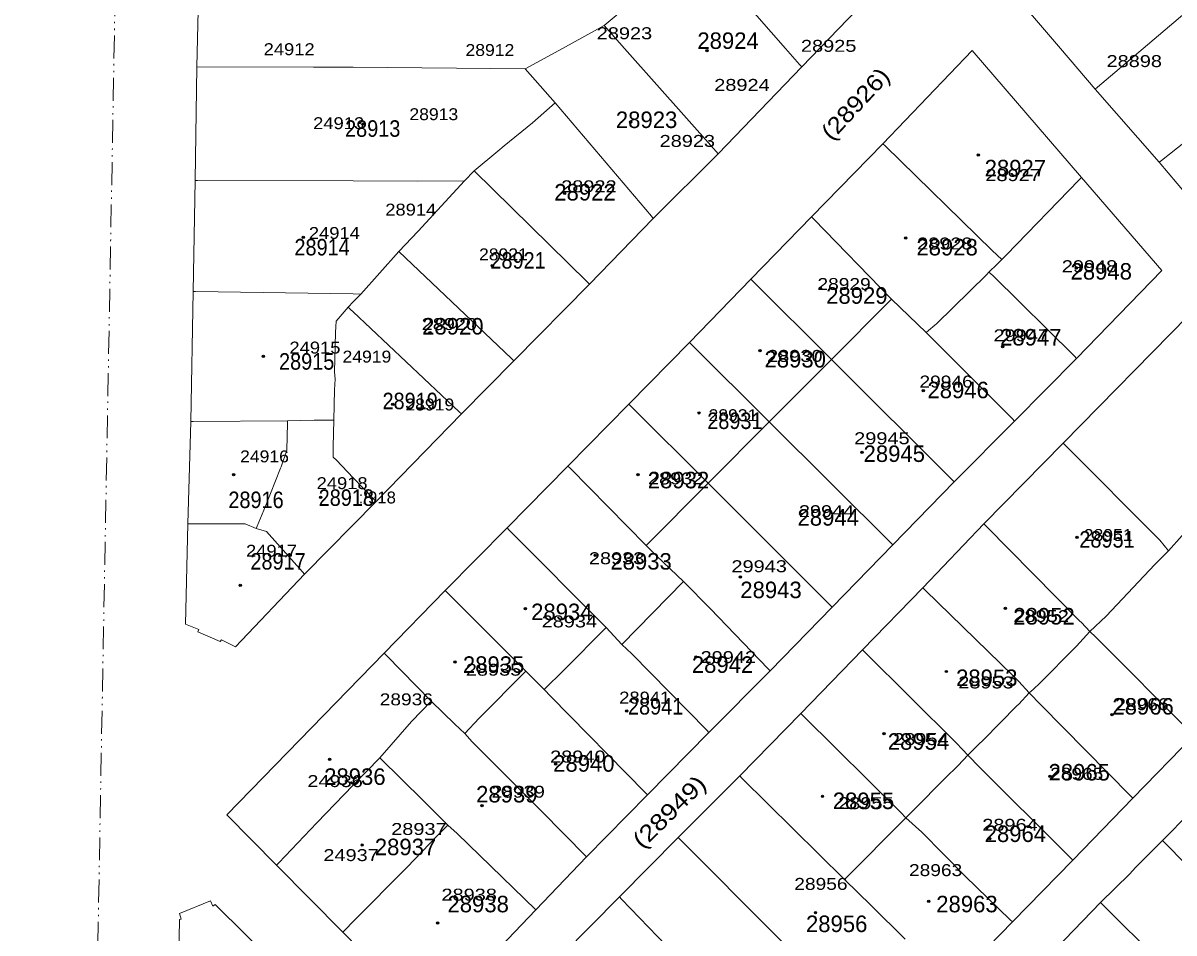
# Model space of a CAD drawing. Extents: x 650553 to 652508, y 239277 to 241647.
# Drawn here: x 650553 to 650803.9, y 240307.2 to 240505.5 of the extents above; entities that cross this region are included whole.
import ezdxf

# ---------------------------------------------------------------- set-up
doc = ezdxf.new("R2010")
doc.units = 0
doc.header["$PDMODE"] = 32
doc.header["$PDSIZE"] = 0.5
doc.linetypes.add('DASH_DOUBLE_DOT', pattern=[9.2, 5, -1.2, 0.3, -1.2, 0.3, -1.2])
for name, color, linetype in [('19', 7, 'Continuous'), ('20', 7, 'Continuous'), ('6', 7, 'Continuous')]:
    doc.layers.add(name, color=color, linetype=linetype)
for name, color, linetype, lineweight in [('3', 7, 'Continuous', 13), ('5', 7, 'Continuous', 13), ('52', 7, 'DASH_DOUBLE_DOT', 13)]:
    doc.layers.add(name, color=color, linetype=linetype, lineweight=lineweight)

msp = doc.modelspace()

# ---------------------------------------------------------------- linework, layer by layer
at = {"layer": '3'}
for p, q in [((650759.9, 240499.51), (650783.69, 240471.83)), ((650761.43, 240286.46), (650787.85, 240313.79))]:
    msp.add_line(p, q, dxfattribs=at)
for points in [[(650641.253, 240637.783), (650611.303, 240672.672), (650607.004, 240673.162), (650594.146, 240646.254), (650593.75, 240621.72), (650592.8, 240596.31), (650592.32, 240570.89), (650591.99, 240545.96), (650591.4, 240517.48), (650590.91, 240496.01)], [(650722.72, 240495.97), (650742.7, 240516.78), (650742.7, 240519.73), (650723.62, 240541.87), (650704.48, 240564.63), (650689.1, 240582.35), (650673.18, 240600.74), (650657.314, 240619.179), (650641.253, 240637.783)], [(650779.1, 240500), (650770.45, 240510.11), (650796.97, 240533.86), (650812.73, 240517.56)], [(650608.29, 240321.94), (650597.42, 240332.94), (650631.74, 240368.15), (650645.05, 240381.8), (650658.5, 240395.47), (650671.76, 240408.96), (650685.08, 240422.45), (650698.26, 240435.88), (650711.63, 240449.67), (650724.89, 240463.26), (650740.42, 240479.21), (650759.9, 240499.51)], [(650779.1, 240500), (650786.71, 240491.11), (650800.67, 240475.19), (650814.34, 240458.95), (650832.82, 240437.45)], [(650588.95, 240396.36), (650588.42, 240374.5), (650591.31, 240373.31), (650591.12, 240372.8), (650595.95, 240370.69), (650596.27, 240371.09), (650599.3, 240369.58), (650614.36, 240385.37), (650629.97, 240401.25), (650648.54, 240420.31), (650659.99, 240431.91), (650676.48, 240448.61), (650690.38, 240462.94), (650704.5, 240476.99), (650722.72, 240495.97)], [(650590.91, 240496.01), (650590.56, 240471.18), (650590.07, 240446.99), (650589.57, 240418.69), (650588.95, 240396.36)], [(650783.69, 240471.83), (650801.22, 240451.56), (650782.65, 240432.42), (650769.138, 240418.737), (650755.97, 240405.5), (650742.6, 240391.77), (650729.33, 240378.23), (650715.86, 240364.33), (650702.52, 240350.9), (650689.09, 240337.28), (650675.83, 240323.79), (650664.78, 240312.19), (650641.7, 240288.01), (650622.73, 240307.37), (650608.29, 240321.94)], [(650779.71, 240413.95), (650806.93, 240441.68), (650809.94, 240441.52), (650829.64, 240418.33), (650839.71, 240406.79), (650850.75, 240393.72), (650839.03, 240381.99), (650828.2, 240370.72), (650808.21, 240350.23), (650794.9, 240336.56), (650781.8, 240323.07), (650768.64, 240309.58), (650755.41, 240295.93), (650741.91, 240281.85), (650728.35, 240268.09)], [(650648.95, 240280.64), (650664.24, 240296.1), (650682.98, 240315.02), (650695.81, 240328), (650709.21, 240341.41), (650722.53, 240355.03), (650735.95, 240368.92), (650749.1, 240382.41), (650762.42, 240396.35), (650779.71, 240413.95)], [(650787.85, 240313.79), (650794.22, 240320.09), (650795.45, 240321.44), (650801.38, 240327.33), (650807.43, 240333.47), (650808.64, 240334.74), (650814.48, 240340.93), (650825.07, 240351.63), (650835.69, 240362.55), (650856.48, 240383.5), (650859.73, 240383.17), (650866.12, 240376.02), (650867.47, 240374.36), (650873.78, 240367.01), (650886.12, 240352.53), (650899.62, 240336.77), (650899.4, 240333.52)], [(650586.52, 240278.39), (650587.14, 240310.13), (650587.44, 240310.18), (650587.09, 240311.44), (650593.87, 240314.16), (650594.4, 240313.05), (650594.86, 240313.35), (650621.45, 240287.07), (650639.57, 240269.49), (650652.76, 240256.68), (650664.23, 240244.84), (650669.94, 240239.41), (650675.92, 240234.11), (650687.16, 240222.82), (650709.87, 240200.29), (650724.82, 240185.65), (650738.96, 240172.09)]]:
    msp.add_lwpolyline(points, dxfattribs=at)
at = {"layer": '5'}
for p, q in [((650670.56, 240500), (650662.43, 240495.54)), ((650763.49, 240451.21), (650764.41, 240450.46)), ((650626.62, 240446.45), (650625, 240446.47)), ((650625, 240444.73), (650623.91, 240443.57)), ((650683.55, 240370.08), (650696.94, 240383.82))]:
    msp.add_line(p, q, dxfattribs=at)
for points in [[(650679.64, 240504.99), (650699.96, 240521.98), (650719.19, 240500)], [(650797.15, 240500), (650814.38, 240514.674), (650814.88, 240515.1)], [(650670.56, 240500), (650679.64, 240504.99), (650684.07, 240500)], [(650684.07, 240500), (650704.056, 240477.49), (650704.5, 240476.99)], [(650719.19, 240500), (650722.282, 240496.47), (650722.72, 240495.97)], [(650786.71, 240491.11), (650787.21, 240491.536), (650797.15, 240500)], [(650830.23, 240498.54), (650829.73, 240498.145), (650801.17, 240475.585), (650800.67, 240475.19)], [(650590.91, 240496.01), (650616.34, 240495.92), (650625, 240495.87)], [(650625, 240495.87), (650662.43, 240495.54), (650669.01, 240488.12)], [(650625, 240444.73), (650626.62, 240446.45), (650634.91, 240455.7), (650639.15, 240460.13), (650649.22, 240471.15), (650651.36, 240473.31), (650656.46, 240477.59), (650657.9, 240478.76), (650664.02, 240483.74), (650669.01, 240488.12)], [(650669.01, 240488.12), (650689.956, 240463.44), (650690.38, 240462.94)], [(650740.42, 240479.21), (650740.92, 240478.72), (650764.21, 240455.91), (650766.32, 240453.97)], [(650651.36, 240473.31), (650675.98, 240449.102), (650676.48, 240448.61)], [(650590.56, 240471.18), (650591.06, 240471.179), (650625, 240471.11)], [(650625, 240471.11), (650638.91, 240471.08), (650649.22, 240471.15)], [(650783.69, 240471.83), (650783.205, 240471.33), (650767.31, 240454.94), (650766.32, 240453.97), (650765.33, 240452.97), (650763.49, 240451.21), (650763.04, 240450.64), (650752.07, 240439.93), (650751.72, 240439.69)], [(650724.89, 240463.26), (650725.375, 240462.76), (650742.29, 240445.32), (650749.83, 240438.07)], [(650634.91, 240455.7), (650659.49, 240432.384), (650659.99, 240431.91)], [(650764.41, 240450.46), (650782.15, 240432.915), (650782.65, 240432.42)], [(650711.63, 240449.67), (650712.13, 240449.172), (650729.19, 240432.178), (650755.97, 240405.5)], [(650590.07, 240446.99), (650590.57, 240446.983), (650625, 240446.47)], [(650729.19, 240432.178), (650741.792, 240444.82), (650742.29, 240445.32)], [(650623.91, 240443.57), (650621.24, 240440.54), (650621.1, 240438.07), (650620.91, 240429.48), (650621.01, 240427.92), (650620.9, 240425.54), (650620.77, 240418.93)], [(650623.91, 240443.57), (650624.41, 240443.098), (650625, 240442.54)], [(650625, 240442.54), (650648.04, 240420.782), (650648.54, 240420.31)], [(650751.72, 240439.69), (650750.33, 240438.499), (650749.83, 240438.07)], [(650749.83, 240438.07), (650768.639, 240419.237), (650769.138, 240418.737)], [(650698.26, 240435.88), (650698.76, 240435.383), (650715.643, 240418.588), (650742.6, 240391.77)], [(650688.8, 240391.66), (650702.319, 240405.222), (650715.643, 240418.588), (650729.19, 240432.178)], [(650685.08, 240422.45), (650685.58, 240421.95), (650702.319, 240405.222)], [(650589.57, 240418.69), (650590.07, 240418.692), (650610.67, 240418.78)], [(650610.67, 240418.78), (650610.66, 240418.28), (650610.54, 240412.42), (650609.24, 240408.77), (650609.13, 240408.53), (650605.85, 240400.24), (650604.055, 240395.86), (650603.85, 240395.36)], [(650610.67, 240418.78), (650616.47, 240418.95), (650620.27, 240418.932), (650620.77, 240418.93)], [(650620.77, 240418.93), (650620.61, 240413.24), (650620.6, 240410.88), (650621.3, 240410.23), (650625, 240406.4)], [(650779.71, 240413.95), (650780.208, 240413.45), (650800.78, 240392.81), (650802.7, 240390.51)], [(650671.76, 240408.96), (650672.252, 240408.46), (650688.8, 240391.66), (650691.1, 240389.42), (650696.94, 240383.82), (650702.83, 240377.81)], [(650625, 240406.4), (650629.487, 240401.75), (650629.97, 240401.25)], [(650702.319, 240405.222), (650728.83, 240378.73), (650729.33, 240378.23)], [(650785.52, 240372.91), (650789.1, 240376.24), (650799.71, 240387.51), (650802.7, 240390.51), (650805.63, 240393.83), (650816.46, 240404.86)], [(650588.95, 240396.36), (650589.45, 240396.36), (650601.41, 240396.37), (650603.85, 240395.36)], [(650603.85, 240395.36), (650606.1, 240394.66), (650613.915, 240385.87), (650614.36, 240385.37)], [(650658.5, 240395.47), (650658.998, 240394.97), (650680.11, 240373.79), (650683.55, 240370.08), (650685.71, 240368.03)], [(650762.42, 240396.35), (650762.913, 240395.85), (650783.25, 240375.23), (650783.74, 240374.83), (650785.52, 240372.91), (650786.82, 240371.66)], [(650749.1, 240382.41), (650749.6, 240381.923), (650768.78, 240363.24), (650770.08, 240361.96), (650772.29, 240359.53), (650774.86, 240356.94)], [(650645.05, 240381.8), (650645.55, 240381.301), (650662.61, 240364.28), (650666.61, 240360.28), (650668.07, 240358.73)], [(650702.83, 240377.81), (650715.377, 240364.83), (650715.86, 240364.33)], [(650666.61, 240360.28), (650670.88, 240364.49), (650680.11, 240373.79)], [(650732.07, 240318.85), (650745.43, 240332.28), (650747.17, 240334.04), (650754.02, 240340.91), (650756.82, 240343.66), (650758.96, 240345.93), (650761.22, 240348.21), (650762.32, 240349.26), (650769.63, 240356.69), (650770.08, 240357.05), (650772.29, 240359.53), (650773.2, 240360.26), (650774.7, 240361.72), (650782.3, 240369.37), (650782.59, 240369.7), (650785.52, 240372.91)], [(650786.82, 240371.66), (650807.711, 240350.73), (650808.21, 240350.23)], [(650631.74, 240368.15), (650632.229, 240367.65), (650641.98, 240357.69), (650647.14, 240352.68), (650649.28, 240350.65), (650650.87, 240348.81), (650665.93, 240333.82), (650675.83, 240323.79)], [(650685.71, 240368.03), (650702.029, 240351.4), (650702.52, 240350.9)], [(650735.95, 240368.92), (650736.45, 240368.423), (650756.39, 240348.6), (650757.79, 240347.14), (650758.96, 240345.93), (650760.09, 240344.79), (650760.36, 240344.44)], [(650649.28, 240350.65), (650652.4, 240354.03), (650662.61, 240364.28)], [(650625, 240339.4), (650630.75, 240345.37), (650637.71, 240353.26), (650641.98, 240357.69)], [(650668.07, 240358.73), (650688.6, 240337.78), (650689.09, 240337.28)], [(650722.53, 240355.03), (650723.03, 240354.534), (650744.32, 240333.43), (650745.43, 240332.28), (650748.94, 240329.16), (650758.33, 240319.53)], [(650774.86, 240356.94), (650794.408, 240337.06), (650794.9, 240336.56)], [(650630.75, 240345.37), (650640.27, 240335.98), (650645.6, 240330.68), (650647.65, 240328.89), (650664.78, 240312.19)], [(650760.36, 240344.44), (650781.3, 240323.568), (650781.8, 240323.07)], [(650709.21, 240341.41), (650709.71, 240340.917), (650732.07, 240318.85), (650737.83, 240313.19), (650745.26, 240305.8)], [(650608.29, 240321.94), (650608.765, 240322.44), (650617.07, 240331.18), (650625, 240339.4)], [(650625, 240309.66), (650636.71, 240321.51), (650643.17, 240328.27), (650645.6, 240330.68)], [(650695.81, 240328), (650696.307, 240327.5), (650717.06, 240306.61), (650721.14, 240302.53), (650725.63, 240298.21), (650726.33, 240297.51)], [(650801.38, 240327.33), (650823.52, 240304.87), (650847.74, 240281.16)], [(650758.33, 240319.53), (650768.14, 240310.063), (650768.64, 240309.58)], [(650682.98, 240315.02), (650683.461, 240314.52), (650699.12, 240298.24), (650707.18, 240290.13), (650712.21, 240284.96)], [(650787.85, 240313.79), (650801.15, 240300.62), (650809.97, 240291.87), (650834.26, 240267.54)], [(650622.73, 240307.37), (650623.226, 240307.87), (650625, 240309.66)]]:
    msp.add_lwpolyline(points, dxfattribs=at)
at = {"layer": '52'}
msp.add_lwpolyline([(650605.404, 240765.589), (650575.102, 240622.376), (650564.111, 240019.547), (650563.292, 239912.239), (650561.967, 239831.306), (650558.948, 239635.138), (650557.76, 239590.469), (650555.824, 239499.761), (650555.114, 239481.758), (650553.994, 239393.396), (650554.019, 239393.395), (650553.222, 239318.763), (650553.006, 239301.006), (650586.911, 239277.281)], dxfattribs=at)
at = {"layer": '6'}
for p in [(650702.084, 240499.485), (650627.257, 240483.545), (650685.422, 240483.965), (650761.206, 240476.74), (650671.083, 240468.365), (650614.1, 240458.815), (650745.397, 240458.64), (650655.29, 240452.61), (650782.589, 240452.125), (650726.776, 240447.719), (650641.683, 240438.005), (650766.496, 240434.973), (650605.402, 240432.84), (650713.626, 240434.129), (650749.229, 240425.41), (650633.577, 240422.41), (650700.325, 240420.551), (650735.881, 240411.974), (650598.9, 240407.07), (650687.06, 240407.055), (650617.851, 240402.16), (650722.532, 240398.409), (650782.731, 240393.43), (650677.714, 240389.52), (650709.361, 240384.776), (650600.351, 240382.975), (650662.511, 240377.875), (650767.133, 240377.94), (650699.649, 240367.36), (650647.142, 240366.225), (650754.277, 240364.17), (650684.586, 240355.535), (650790.371, 240354.735), (650740.688, 240350.6), (650619.828, 240345.045), (650669.069, 240344.035), (650776.875, 240341.3), (650727.259, 240336.94), (650653.06, 240334.94), (650763.705, 240327.755), (650626.927, 240326.37), (650750.425, 240314.105), (650643.376, 240309.345), (650725.736, 240311.63)]:
    msp.add_point(p, dxfattribs=at)

# ---------------------------------------------------------------- texts
at = {"layer": '19'}
for s, p in [('28924', (650699.98, 240499.875)), ('28923', (650682.226, 240482.636)), ('28927', (650762.605, 240472.101)), ('28922', (650668.791, 240466.835)), ('28928', (650747.729, 240454.862)), ('28948', (650781.322, 240449.595)), ('28929', (650728.055, 240444.327)), ('28920', (650639.998, 240437.624)), ('28947', (650765.967, 240435.229)), ('28930', (650714.618, 240430.44)), ('28946', (650750.131, 240423.736)), ('28945', (650736.213, 240409.849)), ('28932', (650689.186, 240404.103)), ('28944', (650721.816, 240395.962)), ('28933', (650681.028, 240386.385)), ('28943', (650709.341, 240380.16)), ('28934', (650663.752, 240375.371)), ('28952', (650768.846, 240374.413)), ('28935', (650648.877, 240363.878)), ('28942', (650698.783, 240363.878)), ('28953', (650756.369, 240361.005)), ('28966', (650790.44, 240354.78)), ('28954', (650741.492, 240347.118)), ('28940', (650668.55, 240342.33)), ('28936', (650618.645, 240339.457)), ('28965', (650776.524, 240340.414)), ('28939', (650651.756, 240335.626)), ('28955', (650729.496, 240334.189)), ('28964', (650762.607, 240327.006)), ('28937', (650629.682, 240324.133)), ('28938', (650645.517, 240311.683)), ('28963', (650752.05, 240311.683)), ('28956', (650723.656, 240307.375))]:
    msp.add_text(s, height=3.6, dxfattribs=at).set_placement(p)
for s, rotation, width, p in [('(28926)', 47.336, 1.15, (650729.274, 240479.68)), ('(28949)', 44.462, 1.2, (650688.011, 240325.346))]:
    msp.add_text(s, height=3.6, rotation=rotation, dxfattribs=dict(at, width=width)).set_placement(p)
at = {"layer": '19', "width": 0.9}
for s, p in [('28913', (650623.202, 240480.722)), ('28914', (650612.164, 240454.863)), ('28921', (650654.875, 240451.99)), ('28915', (650608.806, 240429.962)), ('28919', (650631.36, 240421.343)), ('28931', (650702.142, 240417.032)), ('28916', (650597.769, 240399.794)), ('28918', (650617.444, 240400.273)), ('28951', (650783.242, 240391.174)), ('28917', (650602.568, 240386.386)), ('28941', (650684.867, 240354.78))]:
    msp.add_text(s, height=3.6, dxfattribs=at).set_placement(p)
at = {"layer": '20'}
for s, width, p in [('28923', 1.25, (650678.05, 240501.994)), ('24912', 1.15, (650605.451, 240498.516)), ('28912', 1.1, (650649.45, 240498.337)), ('28925', 1.25, (650722.562, 240499.249)), ('28898', 1.25, (650789.163, 240495.922)), ('28924', 1.25, (650703.661, 240490.733)), ('24913', 1.15, (650616.241, 240482.388)), ('28913', 1.1, (650637.225, 240484.351)), ('28923', 1.25, (650691.752, 240478.522)), ('28927', 1.25, (650762.758, 240471.07)), ('28922', 1.25, (650670.298, 240468.635)), ('28914', 1.15, (650631.959, 240463.55)), ('24914', 1.15, (650615.306, 240458.45)), ('28928', 1.25, (650747.88, 240456.161)), ('28921', 1.1, (650652.398, 240453.797)), ('29948', 1.25, (650779.413, 240451.216)), ('28929', 1.2, (650726.162, 240447.333)), ('28920', 1.25, (650639.885, 240438.604)), ('29947', 1.25, (650764.526, 240436.152)), ('24915', 1.15, (650611.075, 240433.478)), ('24919', 1.1, (650622.646, 240431.512)), ('28930', 1.25, (650715.18, 240431.664)), ('29946', 1.2, (650748.397, 240426.071)), ('28919', 1.1, (650636.352, 240421.069)), ('28931', 1.1, (650702.425, 240418.743)), ('29945', 1.25, (650734.162, 240413.718)), ('24916', 1.1, (650600.322, 240409.763)), ('28932', 1.25, (650689.204, 240404.956)), ('24918', 1.15, (650616.995, 240403.924)), (':/918', 1.05, (650626.16, 240400.805)), ('29944', 1.25, (650722.108, 240397.815)), ('28951', 1.1, (650784.207, 240392.629)), ('24917', 1.15, (650601.611, 240389.184)), ('28933', 1.25, (650676.341, 240387.562)), ('29943', 1.25, (650707.409, 240385.815)), ('28952', 1.25, (650768.872, 240374.957)), ('28934', 1.25, (650666.035, 240373.789)), ('29942', 1.25, (650700.684, 240366.007)), ('28935', 1.25, (650649.517, 240363.261)), ('28953', 1.25, (650756.851, 240360.481)), ('28941', 1.15, (650682.951, 240357.184)), ('28936', 1.2, (650630.75, 240356.801)), ('28966', 1.2, (650791.081, 240355.738)), ('28954', 1.25, (650742.659, 240348.137)), ('28940', 1.25, (650667.883, 240344.334)), ('28965', 1.2, (650776.864, 240340.578)), ('24936', 1.25, (650614.98, 240338.978)), ('28939', 1.2, (650655.137, 240336.667)), ('28955', 1.25, (650730.67, 240334.174)), ('28964', 1.25, (650762.085, 240329.452)), ('28937', 1.25, (650633.251, 240328.545)), ('24937', 1.25, (650618.466, 240322.85)), ('28963', 1.2, (650746.112, 240319.576)), ('28956', 1.2, (650721.107, 240316.572)), ('28938', 1.25, (650644.208, 240314.232))]:
    msp.add_text(s, height=2.6, dxfattribs=dict(at, width=width)).set_placement(p)

doc.saveas('drawing.dxf')
